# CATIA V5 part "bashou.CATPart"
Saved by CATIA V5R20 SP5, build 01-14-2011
Part number: 把手
Bounding box of the stored display mesh (mm): x -29.974 to 35.285, y -19.466 to 19.466, z -19.465 to 19.465
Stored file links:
  E:\180512116\zp\20190505\180512116赵克君\bashou.CATPart
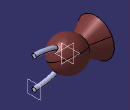
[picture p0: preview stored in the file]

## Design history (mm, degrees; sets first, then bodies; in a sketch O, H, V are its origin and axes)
Body1 (main body)
  Sketch1 on xy-plane, origin (0, 0, 0), H (1, 0, 0), V (0, 1, 0)
    arc A1 centre (0, 0) radius 17 from (17, 0) to (-13.6721, 10.1031) ccw
    point P1 (-29.9744, 0)
    point P2 (-29.9744, 19.5152)
    line L1 (-13.6721, 10.1031) -> (-29.9744, 19.5152)
    construction line L2 (-29.9744, 0) -> (-13.0737, 0)
    line L3 (-29.9744, 19.5152) -> (-29.9744, 0)
    point P4 (-29.9744, 19.5152)
    line L4 (-29.9744, 0) -> (17, 0)
    point P5 (-29.9744, 0)
    point P7 (-29.9744, 0)
    radius A1 = 17
    coincidence: P1 H, P4 L1, P5 L2, P2 P4, P5 P7
    horizontal: L2 H, L4 H
    vertical: L3 V
  Shaft1: profile Sketch1, axis X axis, angle 360
  Sketch2 on zx-plane, origin (0, 0, 0), H (-1, 0, 0), V (0, 0, 1)
    line L1 (31.3594, 16.2916) -> (18.9403, 9.5524)
    line L2 (18.9403, 9.5524) -> (18.9403, 0)
    line L3 (31.3594, 16.2916) -> (31.3594, 0)
    line L4 (18.9403, 0) -> (31.3594, 0)
    vertical: L3 V
    horizontal: L4 H
  Groove1: profile Sketch2, axis X axis, angle 360
  Sketch3 on zx-plane, origin (0, 0, 0), H (-1, 0, 0), V (0, 0, 1)
    arc A1 centre (24.6831, 0) radius 4.5722 from (29.2553, 0) to (20.673, 2.1964) ccw
    point P1 (24.6831, 0)
    point P2 (21.5825, 0)
    line L1 (17.1763, 0) -> (17.1763, 2.1964)
    line L2 (17.1763, 2.1964) -> (20.673, 2.1964)
    point P3 (17.1763, -2.1964)
    line L3 (17.1763, 0) -> (29.2553, 0)
    coincidence: P1 H, P2 H
    vertical: L1 V
    horizontal: L2 H, L3 H
  Shaft2: profile Sketch3, axis X axis, angle 360
  Sketch4 on zx-plane, origin (0, 0, 0), H (-1, 0, 0), V (0, 0, 1)
    point P1 (-35.2854, 0)
    ellipse A1 centre (-35.2854, 0) semi-axes 32.3992, 15.3029 rotation 0 from (-35.2854, -15.3029) to (-35.2854, 15.3029)
    point P2 (-2.8862, 0)
    point P4 (-35.2854, -15.3029)
    coincidence: P1 H, P2 H, A1 P2
  Plane1: type Normal, Curve Sketch4, RefPoint Sketch4.P4
  Sketch5 on Plane1, origin (35.2854, 0, 0), H (0, -1, 0), V (0, 0, 1)
    circle A1 centre (0, -15.3264) radius 2.3227
    point P1 (0, -15.3264)
    coincidence: P1 V
  Rib1: profile Sketch5, centre curve Sketch4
